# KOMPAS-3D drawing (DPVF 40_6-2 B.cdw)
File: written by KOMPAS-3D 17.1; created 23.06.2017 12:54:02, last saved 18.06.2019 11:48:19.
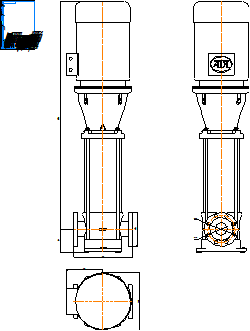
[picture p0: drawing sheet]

Sheet 1: A4, portrait

Title block, sheet 1: name: DPVF 40_6-2 B; material: Внимание! Данный продукт является объектом авторского права ООО «Торговый Дом АДЛ». / Запрещается изменение, копирование, распространение / (в том числе путем копирования на другие сайты и ресурсы в Интернете) / или любое иное использование информации и объектов без предварительного / согласия правообладателя (ООО «Торговый Дом АДЛ»).; scale: 1:1; sheets: 1; organisation: ООО "Торговый дом АДЛ"; sheet format: A4; stored path: C:\Клочков АВ\Насосы\DP PAMS\DPVF 40\Компас 2d\DPVF 40_6-2 B.cdw

Views: Спереди 1
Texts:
  Клочков АВ
  ООО АДЛ ГРУПП
Dimensions and other numbers on the sheet: 365; 223; 350; 209,6; 1390,5; 140; 168,1; 76,2; 1:1; 1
